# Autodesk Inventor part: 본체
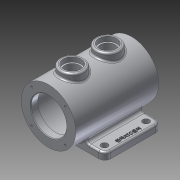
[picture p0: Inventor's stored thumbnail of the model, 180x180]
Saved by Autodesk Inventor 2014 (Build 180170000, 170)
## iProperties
Created: 2014-12
Part Number: 본체
Material: 알루미늄 6061
Document SubType Name: Modeling
Designer: Owner
Density: 2.71 g/cm^3
Appearance: 알루미늄 - 평지
Mass: 1257.02 g
Surface Area: 1039.39 cm^2
Volume: 463.844 cm^3
Author: Owner
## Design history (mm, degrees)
sketch "스케치1"
  geometry: C1 r 46 at (0, 0); 1 further point
  constraints: 1 centre point, 1 coincident
  dimensions: "d0" = 92 diameter of C1
extrude "돌출1" new body sketch "스케치1" stored distance "d1" = 140; taper "d2" = 0 deg
hole "구멍1" diameter "d5" = 60; stored, may be unused: countersink angle "d9" = 90 deg, drill point angle "d11" = 0 deg; dims "d3" = 10, "d4" = 10, "d6" = 6, "d7" = 4, "d8" = 2, "d10" = 12
hole "구멍2" diameter "d14" = 75; stored, may be unused: countersink angle "d18" = 90 deg, drill point angle "d20" = 0 deg; dims "d12" = 10, "d13" = 10, "d15" = 6, "d16" = 4, "d17" = 2, "d19" = 116
hole "구멍3" diameter "d23" = 60; stored, may be unused: countersink angle "d27" = 90 deg, drill point angle "d29" = 0 deg; dims "d21" = 10, "d22" = 10, "d24" = 6, "d25" = 4, "d26" = 2, "d28" = 12
node "작업 평면1"
sketch "스케치2"
  geometry: L1 (-65, -40)-(65, -40); L2 (65, -40)-(65, 55); L3 (65, 55)-(-65, 55); L4 (-65, 55)-(-65, -40); L5 (46, 70)-(-46, 70) reference; 2 further points
  constraints: 8 end point, 2 parallel, 1 horizontal, 1 midpoint, 1 perpendicular, 1 vertical alignment
  dimensions: "d31" = 95 distance of L1.end L2.end; "d32" = 130 distance of L2.end L3.end; "d33" = 15 distance between parallel lines of L3 L5
extrude "돌출2" join sketch "스케치2" distance "d34" = 12; taper "d35" = 0 deg
fillet "모깎기1" dims "d36" = 10
node "작업 평면2"
sketch "스케치3"
  geometry: L1 (-46, -70)-(46, -70) reference; L2 (46, 70)-(-46, 70) reference; C1 r 20 at (0, -30); C2 r 20 at (0, 30); 1 further point
  constraints: 2 centre point, 2 vertical alignment, 1 equal radius
  dimensions: "d38" = 40 diameter of C1; "d39" = 40 distance from line of L1 C1.centre; "d40" = 40 distance from line of L2 C2.centre
extrude "돌출3" join sketch "스케치3" stored distance "d41" = 10; taper "d42" = 0 deg
hole "구멍4" diameter "d45" = 25; stored, may be unused: countersink angle "d49" = 90 deg, drill point angle "d51" = 0 deg; dims "d43" = 10, "d44" = 10, "d46" = 6, "d47" = 30, "d48" = 8, "d50" = 12
hole "구멍5" diameter "d54" = 25; stored, may be unused: countersink angle "d58" = 90 deg, drill point angle "d60" = 0 deg; dims "d52" = 10, "d53" = 10, "d55" = 6, "d56" = 30, "d57" = 8, "d59" = 12
sketch "스케치4"
  geometry: L1 (55, 55)-(25.923, 55) reference; L2 (65, -30)-(65, 45) reference; 2 further points
  dimensions: "d61" = 12.5 distance from line of L1 point (52, 42.5); "d62" = 13 distance from line of L2 point (52, 42.5)
hole "구멍6" sketch "스케치4" at (52, 42.5) diameter "d63" = 11; stored, may be unused: countersink angle "d67" = 90 deg, drill point angle "d69" = 0 deg; dims "d64" = 6, "d65" = 30, "d66" = 8, "d68" = 12
sketch "스케치5"
  geometry: L1 (25.923, -40)-(55, -40) reference; L2 (65, -30)-(65, 45) reference; 2 further points
  dimensions: "d70" = 12.5 distance from line of L1 point (52, -27.5); "d71" = 13 distance from line of L2 point (52, -27.5)
hole "구멍7" sketch "스케치5" at (52, -27.5) diameter "d72" = 11; stored, may be unused: countersink angle "d76" = 90 deg, drill point angle "d78" = 0 deg; dims "d73" = 6, "d74" = 30, "d75" = 8, "d77" = 12
fillet "모깎기2" dims "d79" = 3
fillet "모깎기3" dims "d80" = 3
chamfer "모따기1" distance "d81" = 1; stored, may be unused: second distance "d82" = 2, angle "d83" = 45 deg
sketch "스케치6"
  geometry: L1 (0, 0)-(28.284, 28.284); L2 (0, 0)-(40, 0); C1 r 31 at (0, 0) reference; 1 further point
  constraints: 4 end point, 1 coincident, 1 equal length, 1 horizontal
  dimensions: "d84" = 40 distance of L1.start L1.end; "d85" = 45 deg angle of L2 L1
hole "구멍8" sketch "스케치6" at (28.284, 28.284) diameter "d86" = 3.242; stored, may be unused: countersink angle "d90" = 90 deg, drill point angle "d92" = 118 deg; dims "d87" = 8, "d88" = 30, "d89" = 8, "d91" = 10
fillet "모깎기4" dims "d96" = 5
fillet "모깎기5" dims "d97" = 3
sketch "스케치7"
  geometry: L1 (65, -30)-(65, 45) reference; C1 r 5.5 at (52, -27.5) reference; 2 further points
  constraints: 1 other
  dimensions: "d98" = 35 vertical distance of C1.centre point (57, 7.5); "d99" = 8 distance from line of L1 point (57, 7.5)
feature "엠보싱1" sketch "스케치7" dims "d100" = 1, "d101" = 0
node "솔리드1"
mirror "대칭1"
pattern_circular "원형 패턴1" dims angle "d94" = 360 deg
mirror "대칭2"
other parameters: "d37" = 56
